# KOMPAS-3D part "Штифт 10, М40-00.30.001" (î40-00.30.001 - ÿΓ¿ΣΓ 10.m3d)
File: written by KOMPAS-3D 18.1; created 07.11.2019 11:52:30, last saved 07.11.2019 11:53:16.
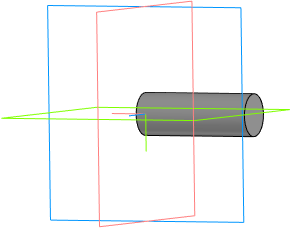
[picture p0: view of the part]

Document properties: Полное имя файла: D:\Magna\Магна Ins\Магна ins 40\3Д\М40-00.30.001 - Штифт 10.m3d

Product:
- Part/product: Штифт 10  | designation М40-00.30.001
    Масса: 0.0172762

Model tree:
1. Эскиз:2
2. Элемент выдавливания:2
     Расстояние 1 = 28

Referenced files in D:\Magna\Магна Ins\Магна ins 40\3Д\: М40-00.30.000 - Корпус.a3d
